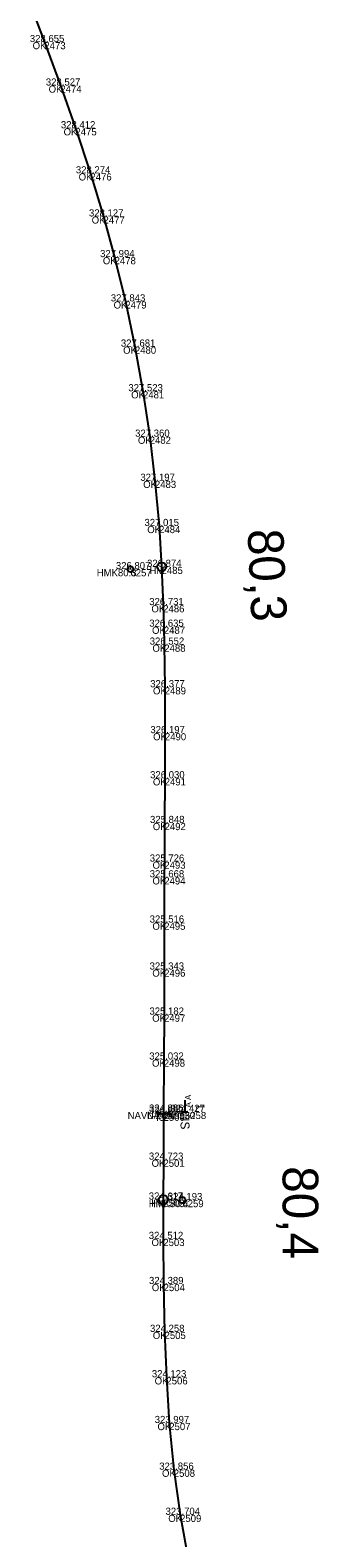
# Model space of a CAD drawing. Extents: x -621782 to -610392, y -1141853 to -1122321.
# Drawn here: x -614255.1 to -614206.5, y -1130453.4 to -1130199.5 of the extents above; entities that cross this region are included whole.
import ezdxf

# ---------------------------------------------------------------- set-up
doc = ezdxf.new("R2010")
doc.units = 0
for name, color, linetype in [('Vrstva 1', 7, 'Continuous'), ('Vrstva 3', 7, 'Continuous'), ('Vrstva 6', 7, 'Continuous'), ('Vrstva 60', 7, 'Continuous'), ('Vrstva 61', 7, 'Continuous'), ('Vrstva 62', 7, 'Continuous'), ('Vrstva 7', 7, 'Continuous')]:
    doc.layers.add(name, color=color, linetype=linetype)

msp = doc.modelspace()

# ---------------------------------------------------------------- linework, layer by layer
at = {"layer": 'Vrstva 1'}
msp.add_lwpolyline([(-614254.96, -1130195.42), (-614252.67, -1130201.49), (-614249.98, -1130208.81), (-614247.45, -1130216.01), (-614244.93, -1130223.6), (-614242.73, -1130230.86), (-614240.86, -1130237.71), (-614239.05, -1130245.17), (-614237.45, -1130252.78), (-614236.09, -1130260.3), (-614234.96, -1130267.95), (-614234.08, -1130275.38), (-614233.38, -1130282.99), (-614232.96, -1130289.87), (-614232.69, -1130296.32), (-614232.58, -1130299.95), (-614232.51, -1130302.97), (-614232.43, -1130310.15), (-614232.4, -1130317.88), (-614232.44, -1130325.48), (-614232.46, -1130333.01), (-614232.5, -1130339.51), (-614232.51, -1130342.16), (-614232.52, -1130349.78), (-614232.53, -1130357.69), (-614232.55, -1130365.28), (-614232.59, -1130372.85), (-614232.63, -1130381.62), (-614232.64, -1130381.97), (-614232.65, -1130389.71), (-614232.67, -1130396.43), (-614232.67, -1130403.06), (-614232.62, -1130410.65), (-614232.46, -1130418.71), (-614232.15, -1130426.36), (-614231.67, -1130434.06), (-614230.91, -1130441.92), (-614229.85, -1130449.52), (-614228.46, -1130457.28)], dxfattribs=at)
at = {"layer": 'Vrstva 3'}
for p, q in [((-614233.63, -1130381.47), (-614233.64, -1130382.47)), ((-614231.64, -1130381.97), (-614233.64, -1130381.97)), ((-614231.63, -1130381.47), (-614231.64, -1130382.47))]:
    msp.add_line(p, q, dxfattribs=at)
at = {"layer": 'Vrstva 6'}
for p, q in [((-614229.03, -1130379.69), (-614229.03, -1130381.67)), ((-614229.53, -1130381.67), (-614228.53, -1130381.67))]:
    msp.add_line(p, q, dxfattribs=at)
at = {"layer": 'Vrstva 60'}
for p, q in [((-614252.67, -1130201.49), (-614252.67, -1130201.49)), ((-614249.98, -1130208.81), (-614249.98, -1130208.81)), ((-614247.45, -1130216.01), (-614247.45, -1130216.01)), ((-614244.93, -1130223.6), (-614244.93, -1130223.6)), ((-614242.73, -1130230.86), (-614242.73, -1130230.86)), ((-614240.86, -1130237.71), (-614240.86, -1130237.71)), ((-614239.05, -1130245.17), (-614239.05, -1130245.17)), ((-614237.45, -1130252.78), (-614237.45, -1130252.78)), ((-614236.09, -1130260.3), (-614236.09, -1130260.3)), ((-614234.96, -1130267.95), (-614234.96, -1130267.95)), ((-614234.08, -1130275.38), (-614234.08, -1130275.38)), ((-614233.38, -1130282.99), (-614233.38, -1130282.99)), ((-614238.2, -1130290.26), (-614238.2, -1130290.26)), ((-614232.96, -1130289.87), (-614232.96, -1130289.87)), ((-614232.69, -1130296.32), (-614232.69, -1130296.32)), ((-614232.58, -1130299.95), (-614232.58, -1130299.95)), ((-614232.51, -1130302.97), (-614232.51, -1130302.97)), ((-614232.43, -1130310.15), (-614232.43, -1130310.15)), ((-614232.4, -1130317.88), (-614232.4, -1130317.88)), ((-614232.44, -1130325.48), (-614232.44, -1130325.48)), ((-614232.46, -1130333.01), (-614232.46, -1130333.01)), ((-614232.5, -1130339.51), (-614232.5, -1130339.51)), ((-614232.51, -1130342.16), (-614232.51, -1130342.16)), ((-614232.52, -1130349.78), (-614232.52, -1130349.78)), ((-614232.53, -1130357.69), (-614232.53, -1130357.69)), ((-614232.55, -1130365.28), (-614232.55, -1130365.28)), ((-614232.59, -1130372.85), (-614232.59, -1130372.85)), ((-614232.64, -1130381.97), (-614232.64, -1130381.97)), ((-614232.63, -1130381.62), (-614232.63, -1130381.62)), ((-614229.03, -1130381.67), (-614229.03, -1130381.67)), ((-614232.65, -1130389.71), (-614232.65, -1130389.71)), ((-614232.67, -1130396.43), (-614232.67, -1130396.43)), ((-614229.46, -1130396.51), (-614229.46, -1130396.51)), ((-614232.67, -1130403.06), (-614232.67, -1130403.06)), ((-614232.62, -1130410.65), (-614232.62, -1130410.65)), ((-614232.46, -1130418.71), (-614232.46, -1130418.71)), ((-614232.15, -1130426.36), (-614232.15, -1130426.36)), ((-614231.67, -1130434.06), (-614231.67, -1130434.06)), ((-614230.91, -1130441.92), (-614230.91, -1130441.92)), ((-614229.85, -1130449.52), (-614229.85, -1130449.52))]:
    msp.add_line(p, q, dxfattribs=at)
at = {"layer": 'Vrstva 7'}
for p, q in [((-614238.21, -1130290.21), (-614238.2, -1130290.31)), ((-614229.46, -1130396.46), (-614229.46, -1130396.56))]:
    msp.add_line(p, q, dxfattribs=at)
for centre, radius in [((-614238.2, -1130290.26), 0.5), ((-614232.96, -1130289.87), 0.75), ((-614232.67, -1130396.43), 0.75), ((-614229.46, -1130396.51), 0.5)]:
    msp.add_circle(centre, radius, dxfattribs=at)

# ---------------------------------------------------------------- texts
at = {"layer": 'Vrstva 3'}
msp.add_text('IS', height=1.5, rotation=269.8815, dxfattribs=at).set_placement((-614229.77, -1130382.72))
at = {"layer": 'Vrstva 6'}
for s, height, rotation, p in [('  A A ', 1, 89.8815, (-614228.03, -1130381.67)), ('L', 1.5, 269.8815, (-614227.2, -1130380.55))]:
    msp.add_text(s, height=height, rotation=rotation, dxfattribs=at).set_placement(p)
at = {"layer": 'Vrstva 60'}
for s, p in [('2473', (-614252.67, -1130202.69)), ('2474', (-614249.98, -1130210.01)), ('2475', (-614247.45, -1130217.21)), ('2476', (-614244.93, -1130224.8)), ('2477', (-614242.73, -1130232.06)), ('2478', (-614240.86, -1130238.91)), ('2479', (-614239.05, -1130246.37)), ('2480', (-614237.45, -1130253.98)), ('2481', (-614236.09, -1130261.5)), ('2482', (-614234.96, -1130269.15)), ('2483', (-614234.08, -1130276.58)), ('2484', (-614233.38, -1130284.19)), ('6257', (-614238.2, -1130291.46)), ('2485', (-614232.96, -1130291.07)), ('2486', (-614232.69, -1130297.53)), ('2487', (-614232.58, -1130301.15)), ('2488', (-614232.51, -1130304.17)), ('2489', (-614232.43, -1130311.35)), ('2490', (-614232.4, -1130319.08)), ('2491', (-614232.44, -1130326.68)), ('2492', (-614232.46, -1130334.21)), ('2493', (-614232.5, -1130340.71)), ('2494', (-614232.51, -1130343.36)), ('2495', (-614232.52, -1130350.99)), ('2496', (-614232.53, -1130358.89)), ('2497', (-614232.55, -1130366.48)), ('2498', (-614232.59, -1130374.05)), ('2500', (-614232.64, -1130383.17)), ('2499', (-614232.63, -1130382.82)), ('6258', (-614229.03, -1130382.87)), ('2501', (-614232.65, -1130390.91)), ('2502', (-614232.67, -1130397.63)), ('6259', (-614229.46, -1130397.71)), ('2503', (-614232.67, -1130404.26)), ('2504', (-614232.62, -1130411.85)), ('2505', (-614232.46, -1130419.91)), ('2506', (-614232.15, -1130427.56)), ('2507', (-614231.67, -1130435.26)), ('2508', (-614230.91, -1130443.12)), ('2509', (-614229.85, -1130450.72))]:
    msp.add_text(s, height=1.2, dxfattribs=at).set_placement(p)
at = {"layer": 'Vrstva 61'}
for s, p in [('328.655', (-614255.12, -1130201.49)), ('328.527', (-614252.43, -1130208.81)), ('328.412', (-614249.9, -1130216.01)), ('328.274', (-614247.38, -1130223.6)), ('328.127', (-614245.18, -1130230.86)), ('327.994', (-614243.31, -1130237.71)), ('327.843', (-614241.5, -1130245.17)), ('327.681', (-614239.81, -1130252.78)), ('327.523', (-614238.55, -1130260.3)), ('327.360', (-614237.41, -1130267.95)), ('327.197', (-614236.53, -1130275.38)), ('327.015', (-614235.84, -1130282.99)), ('326.807', (-614240.65, -1130290.26)), ('326.874', (-614235.41, -1130289.87)), ('326.731', (-614235.04, -1130296.32)), ('326.635', (-614235.04, -1130299.95)), ('326.552', (-614234.96, -1130302.97)), ('326.377', (-614234.88, -1130310.15)), ('326.197', (-614234.85, -1130317.88)), ('326.030', (-614234.89, -1130325.48)), ('325.848', (-614234.91, -1130333.01)), ('325.726', (-614234.95, -1130339.51)), ('325.668', (-614234.96, -1130342.16)), ('325.516', (-614234.97, -1130349.78)), ('325.343', (-614234.98, -1130357.69)), ('325.182', (-614235, -1130365.28)), ('325.032', (-614235.04, -1130372.85)), ('324.886', (-614235.09, -1130381.62)), ('324.427', (-614231.48, -1130381.67)), ('324.882', (-614235.08, -1130381.97)), ('324.723', (-614235.1, -1130389.71)), ('324.617', (-614235.12, -1130396.43)), ('324.193', (-614231.91, -1130396.51)), ('324.512', (-614235.12, -1130403.06)), ('324.389', (-614235.08, -1130410.65)), ('324.258', (-614234.91, -1130418.71)), ('324.123', (-614234.6, -1130426.36)), ('323.997', (-614234.12, -1130434.06)), ('323.856', (-614233.36, -1130441.92)), ('323.704', (-614232.3, -1130449.52))]:
    msp.add_text(s, height=1.2, dxfattribs=at).set_placement(p)
at = {"layer": 'Vrstva 62'}
for s, p in [('OK', (-614254.65, -1130202.69)), ('OK', (-614251.96, -1130210.01)), ('OK', (-614249.44, -1130217.21)), ('OK', (-614246.91, -1130224.8)), ('OK', (-614244.72, -1130232.06)), ('OK', (-614242.84, -1130238.91)), ('OK', (-614241.03, -1130246.37)), ('OK', (-614239.43, -1130253.98)), ('OK', (-614238.08, -1130261.5)), ('OK', (-614236.94, -1130269.15)), ('OK', (-614236.06, -1130276.58)), ('OK', (-614235.37, -1130284.19)), ('HMK80.3', (-614243.87, -1130291.46)), ('HM', (-614234.99, -1130291.07)), ('OK', (-614234.67, -1130297.53)), ('OK', (-614234.57, -1130301.15)), ('OK', (-614234.5, -1130304.17)), ('OK', (-614234.41, -1130311.35)), ('OK', (-614234.39, -1130319.08)), ('OK', (-614234.42, -1130326.68)), ('OK', (-614234.44, -1130334.21)), ('OK', (-614234.48, -1130340.71)), ('OK', (-614234.5, -1130343.36)), ('OK', (-614234.5, -1130350.99)), ('OK', (-614234.52, -1130358.89)), ('OK', (-614234.54, -1130366.48)), ('OK', (-614234.57, -1130374.05)), ('NAVL-Žďár-130', (-614238.67, -1130382.87)), ('NAV', (-614235.45, -1130382.82)), ('IS', (-614233.86, -1130383.17)), ('OK', (-614234.64, -1130390.91)), ('HMK80.4', (-614235.12, -1130397.71)), ('HM', (-614234.71, -1130397.63)), ('OK', (-614234.65, -1130404.26)), ('OK', (-614234.61, -1130411.85)), ('OK', (-614234.44, -1130419.91)), ('OK', (-614234.13, -1130427.56)), ('OK', (-614233.65, -1130435.26)), ('OK', (-614232.89, -1130443.12)), ('OK', (-614231.84, -1130450.72))]:
    msp.add_text(s, height=1.2, dxfattribs=at).set_placement(p)
at = {"layer": 'Vrstva 7'}
for s, rotation, p in [('80,3', 272.4314, (-614218.5, -1130283.59)), ('80,4', 270.0259, (-614212.61, -1130390.81))]:
    msp.add_text(s, height=6, rotation=rotation, dxfattribs=at).set_placement(p)

doc.saveas('drawing.dxf')
